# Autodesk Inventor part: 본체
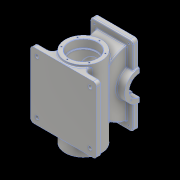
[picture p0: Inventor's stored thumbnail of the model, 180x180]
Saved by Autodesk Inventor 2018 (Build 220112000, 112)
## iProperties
Created: 2023-07
Part Number: 본체
Material: 알루미늄 6061
Document SubType Name: Modeling
Designer: home
Density: 2.7 g/cm^3
Appearance: 알루미늄 - 평지
Mass: 5727.74 g
Surface Area: 2844.83 cm^2
Volume: 2121.38 cm^3
Author: home
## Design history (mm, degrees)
sketch "스케치1"
  geometry: L1 (-90, 100)-(90, 100); L2 (100, 90)-(100, -90); L3 (90, -100)-(-90, -100); L4 (-100, -90)-(-100, 90); L5 (-100, 100)-(100, -100); L6 (100, 100)-(-100, -100); A1 r 10 centre (90, 90) between (100, 90) and (90, 100); A2 r 10 centre (90, -90) between (90, -100) and (100, -90); A3 r 10 centre (-90, -90) between (-100, -90) and (-90, -100); A4 r 10 centre (-90, 90) between (-90, 100) and (-100, 90); 1 further point
  constraints: 12 end point, 8 point on circle, 8 point on line, 8 tangent, 4 centre point, 3 equal radius, 2 midpoint, 2 parallel, 1 horizontal, 1 perpendicular
  dimensions: "d0" = 200 distance of L5.end L6.end; "d1" = 200 distance of L6.start L5.end; "d2" = 10 radius of A1
extrude "돌출1" new body sketch "스케치1" distance "d3" = 15; taper "d4" = 0 deg
sketch "스케치2"
  geometry: L1 (-90, 0)-(90, 0) reference; C1 r 55 at (0, 60); 1 further point
  constraints: 1 centre point
  dimensions: "d5" = 110 diameter of C1; "d6" = 60 distance from line of L1 C1.centre; "d7" = 108.16654 distance of L1.end C1.centre
extrude "돌출2" join sketch "스케치2" distance "d8" = 107; taper "d10" = 0 deg; dims "d9" = 135, "d11" = 0
node "작업 평면1"
sketch "스케치3"
  geometry: L1 (55, 120)-(-55, 120); L2 (-65, 110)-(-65, -110); L3 (-55, -120)-(55, -120); L4 (65, -110)-(65, 110); L5 (65, 120)-(-65, -120); L6 (-65, 120)-(65, -120); A1 r 10 centre (-55, 110) between (-55, 120) and (-65, 110); A2 r 10 centre (-55, -110) between (-65, -110) and (-55, -120); A3 r 10 centre (55, -110) between (55, -120) and (65, -110); A4 r 10 centre (55, 110) between (65, 110) and (55, 120); 1 further point
  constraints: 12 end point, 8 point on circle, 8 point on line, 8 tangent, 4 centre point, 3 equal radius, 2 midpoint, 2 parallel, 1 horizontal, 1 perpendicular
  dimensions: "d13" = 130 distance of L6.end L5.end; "d14" = 240 distance of L5.end L6.start; "d15" = 10 radius of A1 (derived)
extrude "돌출3" join sketch "스케치3" distance "d16" = 15; taper "d17" = 0 deg
sketch "스케치4"
  geometry: L1 (160, 110)-(160, -110) reference; L2 (160, -110)-(145, -110) reference; L3 (145, 110)-(145, -110) reference; L4 (160, 110)-(145, 110) reference; L5 (160, 100)-(160, -100); L6 (160, 110)-(160, -110) reference; A1 r 100 centre (160, 0) between (160, 100) and (160, -100); 1 further point
  constraints: 3 point on line, 2 end point, 2 point on circle, 1 centre point, 1 midpoint
  dimensions: "d18" = 100 radius of A1
extrude "돌출4" join sketch "스케치4" stored distance "d19" = 90; taper "d20" = 0 deg
sketch "스케치5"
  geometry: L1 (160, 110)-(160, -110) reference; L2 (160, -110)-(145, -110) reference; L3 (145, 110)-(145, -110) reference; L4 (160, 110)-(145, 110) reference; L5 (160, 110)-(160, -110) reference; L6 (160, 45)-(160, -45); A1 r 45 centre (160, 0) between (160, 45) and (160, -45); 1 further point
  constraints: 2 end point, 2 point on circle, 2 point on line, 1 centre point, 1 midpoint
  dimensions: "d21" = 45 radius of A1
extrude "돌출5" join sketch "스케치5" stored distance "d22" = 140; taper "d23" = 0 deg
sketch "스케치6"
  geometry: L1 (160, 45)-(160, -45) reference; L2 (160, 110)-(160, 45) reference; L3 (160, 87)-(160, -87); A1 r 87 centre (160, 0) between (160, 87) and (160, -87); 2 further points
  constraints: 2 end point, 2 midpoint, 2 point on circle, 1 centre point, 1 collinear, 1 horizontal alignment, 1 point on line
  dimensions: "d24" = 87 radius of A1
extrude "돌출6" cut sketch "스케치6" stored distance "d25" = 64; taper "d26" = 0 deg
hole "구멍1" diameter "d29" = 55; stored, may be unused: countersink angle "d33" = 90 deg, drill point angle "d35" = 0 deg; dims "d27" = 10, "d28" = 10, "d30" = 6, "d31" = 62, "d32" = 23, "d34" = 50
sketch "스케치7"
  geometry: L1 (-31, 160)-(-45, 160) reference; L2 (45, 160)-(31, 160) reference; A1 r 31 centre (0, 160) between (-31, 160) and (31, 160) reference; A2 r 45 centre (0, 160) between (-45, 160) and (45, 160) reference; 2 further points
  dimensions: "d38" = 26.16295 distance from line of point (26.163, 133.837) L1; "d39" = 32.23871 distance of L2.start point (26.163, 133.837)
hole "구멍2" sketch "스케치7" at (26.163, 133.837) diameter "d40" = 4.134; stored, may be unused: countersink angle "d44" = 90 deg, drill point angle "d46" = 118 deg; dims "d41" = 10, "d42" = 62, "d43" = 23, "d45" = 12
hole "구멍3" diameter "d52" = 77; stored, may be unused: countersink angle "d56" = 90 deg, drill point angle "d58" = 0 deg; dims "d53" = 10, "d54" = 85, "d55" = 25, "d57" = 242, "d114" = 10, "d115" = 10
hole "구멍4" diameter "d61" = 85; stored, may be unused: countersink angle "d65" = 90 deg, drill point angle "d67" = 0 deg; dims "d59" = 10, "d60" = 10, "d62" = 10, "d63" = 85, "d64" = 25, "d66" = 25
sketch "스케치8"
  geometry: C1 r 42.5 at (0, 0) reference; C2 r 55 at (0, 0) reference; C3 r 55 at (0, 0) reference; 2 further points
  dimensions: "d71" = 48.5 distance of C1.centre point (0, 48.5); "d72" = 108.5 distance of point (0, -60) point (0, 48.5)
hole "구멍5" sketch "스케치8" at (0, 48.5) diameter "d73" = 4.134; stored, may be unused: countersink angle "d77" = 90 deg, drill point angle "d79" = 118 deg; dims "d74" = 10, "d75" = 85, "d76" = 25, "d78" = 12
sketch "스케치9"
  geometry: C1 r 42.5 at (0, 0) reference; C2 r 55 at (0, 0) reference; 2 further points
  dimensions: "d84" = 48.5 distance of C1.centre point (0, 48.5); "d85" = 108.5 distance of point (0, -60) point (0, 48.5)
hole "구멍6" sketch "스케치9" at (0, 48.5) diameter "d86" = 4.134; stored, may be unused: countersink angle "d90" = 90 deg, drill point angle "d92" = 118 deg; dims "d87" = 10, "d88" = 85, "d89" = 25, "d91" = 12
sketch "스케치10"
  geometry: L1 (-100, -90)-(-100, 90) reference; L2 (-90, 100)-(90, 100) reference; L3 (100, 90)-(100, -90) reference; L4 (90, -100)-(-90, -100) reference; L5 (-100, 0)-(100, 0); L6 (-90, 100)-(90, 100) reference; L7 (0, 100)-(0, -100); L8 (31.623, -100)-(-31.623, -100) reference; A1 r 10 centre (-90, 90) between (-90, 100) and (-100, 90) reference; A2 r 10 centre (90, 90) between (100, 90) and (90, 100) reference; A3 r 10 centre (90, -90) between (90, -100) and (100, -90) reference; A4 r 10 centre (-90, -90) between (-100, -90) and (-90, -100) reference; 5 further points
  constraints: 4 end point, 4 midpoint, 2 horizontal alignment, 2 vertical alignment
  dimensions: "d96" = 160 distance of point (80, -80) point (-80, -80); "d97" = 160 distance of point (80, 80) point (80, -80); "d98" = 80 distance from line of point (80, -80) L5; "d99" = 80 distance from line of point (-80, -80) L7
hole "구멍7" sketch "스케치10" at (-80, 80), (80, 80), (80, -80), (-80, -80) diameter "d100" = 11; stored, may be unused: countersink angle "d104" = 90 deg, drill point angle "d106" = 0 deg; dims "d101" = 10, "d102" = 28, "d103" = 2, "d105" = 15
fillet "모깎기1" dims "d107" = 1.1
fillet "모깎기2" dims "d108" = 15
fillet "모깎기3" dims "d109" = 3
fillet "모깎기4" dims "d110" = 3
fillet "모깎기5" dims "d111" = 3
fillet "모깎기6" dims "d112" = 1
fillet "모깎기7" dims "d113" = 3
fillet "모깎기8" dims "d116" = 3
sketch "스케치11"
  geometry: L1 (-55, 120)-(55, 120) reference; L2 (55, -120)-(-55, -120) reference; L3 (65, -48)-(65, -110) reference; L4 (-65, -110)-(-65, -48) reference; L5 (-65, 48)-(-65, 110) reference; L6 (65, 110)-(65, 48) reference; 5 further points
  constraints: 2 horizontal alignment, 2 vertical alignment
  dimensions: "d117" = 104 distance of point (-52, 107) point (52, 107); "d118" = 214 distance of point (-52, -107) point (-52, 107); "d119" = 52 horizontal distance of point (0, 0) point (52, 107); "d120" = 107 vertical distance of point (0, 0) point (-52, 107)
hole "구멍8" sketch "스케치11" at (-52, 107), (52, -107), (-52, -107), (52, 107) diameter "d121" = 4.917; stored, may be unused: countersink angle "d125" = 90 deg, drill point angle "d127" = 0 deg; dims "d122" = 15, "d123" = 28, "d124" = 2, "d126" = 15
sketch "스케치12"
  geometry: L1 (100, -90)-(100, 90) reference; 2 further points
  constraints: 1 horizontal alignment, 1 other
  dimensions: "d128" = 15 distance from line of L1 point (85, 0)
feature "엠보싱1" sketch "스케치12" dims "d0" = 200, "d1" = 200, "d2" = 10, "d7" = 108.16654, "d129" = 0.5, "d130" = 0
chamfer "모따기1" distance "d131" = 1; stored, may be unused: second distance "d132" = 2, angle "d133" = 45 deg
node "솔리드1"
pattern_circular "원형 패턴1" dims angle "d48" = -90 deg
mirror "미러1"
pattern_circular "원형 패턴2" dims angle "d81" = 360 deg
pattern_circular "원형 패턴3" dims angle "d94" = 360 deg
node "투영된 루프1"
node "투영된 루프2"
node "투영된 루프3"
node "투영된 루프4"
node "투영된 루프5"
node "투영된 루프6"
